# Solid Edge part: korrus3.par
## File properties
Author: Indrek
Template: Normal.par
Last saved by: Indrek
Revision: 11
Application: Solid Edge
Density: 7750,000 kg/m^3
Accuracy: 0,990
Material: Stainless Steel, 420
Face Style: Steel
Fill Style: ANSI32(Steel)
Virtual Style: Stainless steel
Coef. of Thermal Exp: 1e-05
Thermal Conductivity: 25.0
Specific Heat: 502.0
Modulus of Elasticity: 19994795300.0
Poission's Ratio: 0.29
Yield Stress: 344737850.0
Ultimate Stress: 655001915.0
Elongation: 0.0
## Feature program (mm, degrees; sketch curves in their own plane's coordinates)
make body feature "unnamed MakeBodyFeature 1"
sketch for "ExtrudedProtrusion_1" plane through (0, -392.2606, -246.4564) normal (0, -1, 0) x-axis (1, 0, 0)
  line (-90.7432, 47.25) -> (90.7431, 47.25)
extrude "ExtrudedProtrusion_1" add finite 189.0147 along +normal
sketch for "ExtrudedCutout_3" plane through (0, -290.6352, -199.2064) normal (0, 0, 1) x-axis (-1, 0, 0)
  line (145.5469, 330.1731) -> (178.3941, 235.8643)
  line (178.3941, 235.8643) -> (98.2107, 226.7853)
  line (-160.2715, 235.8643) -> (-98.1997, 222.207)
  line (-160.2715, 235.8643) -> (-57, 370.9489)
  line (-57, 370.9489) -> (145.5469, 330.1731)
extrude "ExtrudedCutout_3" cut finite 101.9235 along -normal
fillet "Round_2" radius 10
sketch for "ExtrudedCutout_4" plane through (0, 0, -246.4564) normal (0, 1, 0) x-axis (-1, 0, 0)
  line (273.4104, -26.8609) -> (-272.8495, -26.8609)
  line (-272.8495, -26.8609) -> (-272.8495, -55.6215)
  line (-272.8495, -55.6215) -> (273.4104, -55.6215)
  line (273.4104, -55.6215) -> (273.4104, -26.8609)
extrude "ExtrudedCutout_4" cut finite 586.9261 along -normal
sketch for "ExtrudedCutout_5" plane through (0.0001, 0, -236.2639) normal (0, 1, 0) x-axis (-1, 0, 0)
extrude "ExtrudedCutout_5" cut finite 612.1091 along -normal
sketch for "ExtrudedProtrusion_2" plane through (0, -285.6351, -199.2064) normal (0, 0, 1) x-axis (-1, 0, 0)
extrude "ExtrudedProtrusion_2" add finite 2 along +normal
thinwall "Thinwall_10"  Thickness = 4 mm
sketch for "ExtrudedCutout_6" plane through (-6.6714, -288.6376, -234.3174) normal (0, 0, 1) x-axis (-1, 0, 0)
  line (0, -285.6351) -> (0, -275.6351)
  line (0, -275.6351) -> (2, -275.6351)
  line (2, -275.6351) -> (2, -285.6351)
  line (2, -285.6351) -> (0, -285.6351)
extrude "ExtrudedCutout_6" cut finite 4.4955 along -normal
sketch for "unnamed Cutout 1" plane through (90.7431, -684.4096, -199.2064) normal (0, -1, 0) x-axis (-1, 0, 0)
  line (90.6148, 13.763) -> (161.9925, 13.763)
  line (161.9925, 13.763) -> (161.9925, 32.2225)
  line (161.9925, 32.2225) -> (90.6148, 32.2225)
  line (19.2372, 32.2225) -> (90.6148, 32.2225)
  line (19.2372, 13.763) -> (19.2372, 32.2225)
  line (90.6148, 13.763) -> (19.2372, 13.763)
extrude "unnamed Cutout 1" cut along -normal
Other named dimensions: "OffsetSurface_3": Distance = 4 mm | "OffsetSurface_4": Distance = 3.175 mm
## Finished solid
Body 1: sheet body, 1 face, 4 edges, 4 vertices.
  Faces by surface: cylinder 1
  Edges by curve: circle 2, curve on surface 2
Body 2: sheet body, 1 face, 4 edges, 4 vertices.
  Faces by surface: cylinder 1
  Edges by curve: circle 2, curve on surface 2
Body 3: solid body, 35 faces, 96 edges, 64 vertices.
  Faces by surface: plane 19, blend 4, offset 4, cylinder 2, spline 2, swept 2, torus 2
  Edges by curve: line 46, intersection 30, circle 14, curve on surface 2, ellipse 2, spline 2
Body 4: solid body, 4 faces, 6 edges, 4 vertices.
  Faces by surface: plane 3, spline 1
  Edges by curve: line 2, spline 2, curve on surface 1, ellipse 1
Bounding box of the edges (mm; curved faces can reach further): 437.086 x 584.450 x 96.500, from (-218.5431, -584.4503, -293.7064) to (218.5431, 0, -197.2064).
Cylindrical faces by radius (mm): R102.0217 x2, R106.0217 x1, R109.1967 x1
Toroidal faces (ring radius, tube radius in mm): R96.0217 r6 x1, R96.0217 r10 x1
Planar faces by outward normal: +x 3, +y 3, +z 6, -x 3, -y 3, -z 4
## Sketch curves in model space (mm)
line (-71.2494, -684.4096, -212.9693) -> (-71.2494, -684.4096, -231.4288)
line (-71.2494, -684.4096, -231.4288) -> (0.1283, -684.4096, -231.4288)
line (71.506, -684.4096, -231.4288) -> (0.1283, -684.4096, -231.4288)
line (71.506, -684.4096, -212.9693) -> (71.506, -684.4096, -231.4288)
line (0.1283, -684.4096, -212.9693) -> (71.506, -684.4096, -212.9693)
line (0.1283, -684.4096, -212.9693) -> (-71.2494, -684.4096, -212.9693)
line (-71.2494, -549.1746, -231.4288) -> (-71.2494, -554.6041, -231.4288)
arc centre (-0.935, -475.2536, -231.4288) radius 106.0217 from (-71.2494, -554.6041, -231.4288) through (-38.0388, -574.5708, -231.4288) to (0.1283, -581.2699, -231.4288)
arc centre (-0.935, -475.2536, -231.4288) radius 106.0217 from (0.1283, -581.2699, -231.4288) through (38.5016, -573.6678, -231.4288) to (71.506, -552.6674, -231.4288)
line (71.506, -547.0918, -231.4288) -> (71.506, -552.6674, -231.4288)
arc centre (-0.935, -475.2536, -231.4288) radius 102.0217 from (71.506, -547.0918, -231.4288) through (38.794, -569.2218, -231.4288) to (0.1283, -577.2697, -231.4288)
arc centre (-0.935, -475.2536, -231.4288) radius 102.0217 from (0.1283, -577.2697, -231.4288) through (-38.3016, -570.186, -231.4288) to (-71.2494, -549.1746, -231.4288)
ellipse centre (0, -392.2606, -225.3386) radii 98.1997, 68.3678 from (0.0062, -392.2606, -293.7064) through (83.2252, -392.2606, -261.6269) to (90.7431, -392.2606, -199.2064)
ellipse centre (0, -392.2606, -225.3386) radii 98.1997, 68.3678 from (-90.7431, -392.2606, -199.2064) through (5.838, -392.2606, -293.5855) to (90.7431, -392.2606, -199.2064)
line (-90.7431, -392.2606, -199.2064) -> (90.7431, -392.2606, -199.2064)
line (44.3041, -171.7493, -199.2064) -> (181.7265, -171.7493, -199.2064)
ellipse centre (0, -171.7493, -225.3386) radii 196.6594, 68.3678 from (-181.7265, -171.7493, -199.2064) through (11.6914, -171.7493, -293.5855) to (181.7265, -171.7493, -199.2064)
line (-181.7265, -171.7493, -199.2064) -> (181.7265, -171.7493, -199.2064)
ellipse centre (0, 0, -225.3386) radii 218.5431, 68.3678 from (-201.9485, 0, -199.2064) through (12.9924, 0, -293.5855) to (201.9485, 0, -199.2064)
line (201.9485, 0, -199.2064) -> (-201.9485, 0, -199.2064)
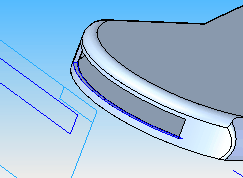
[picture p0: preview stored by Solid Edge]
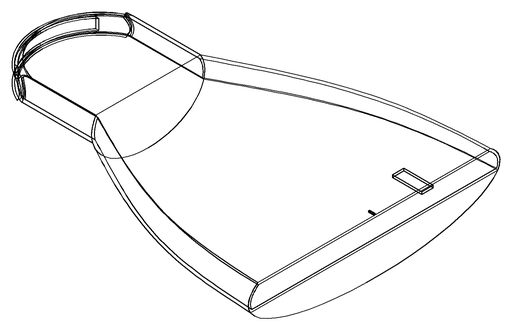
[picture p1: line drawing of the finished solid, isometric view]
